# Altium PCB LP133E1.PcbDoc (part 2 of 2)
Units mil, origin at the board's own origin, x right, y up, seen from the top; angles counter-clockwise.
Board outline 3991.15 x 4704.13 mil, 4 copper layers (Top Layer, L02_GND1, L03_GND2, Bottom Layer), stack 58.396 mil thick; 74 components, 22 nets, 180 pads, 42 vias.
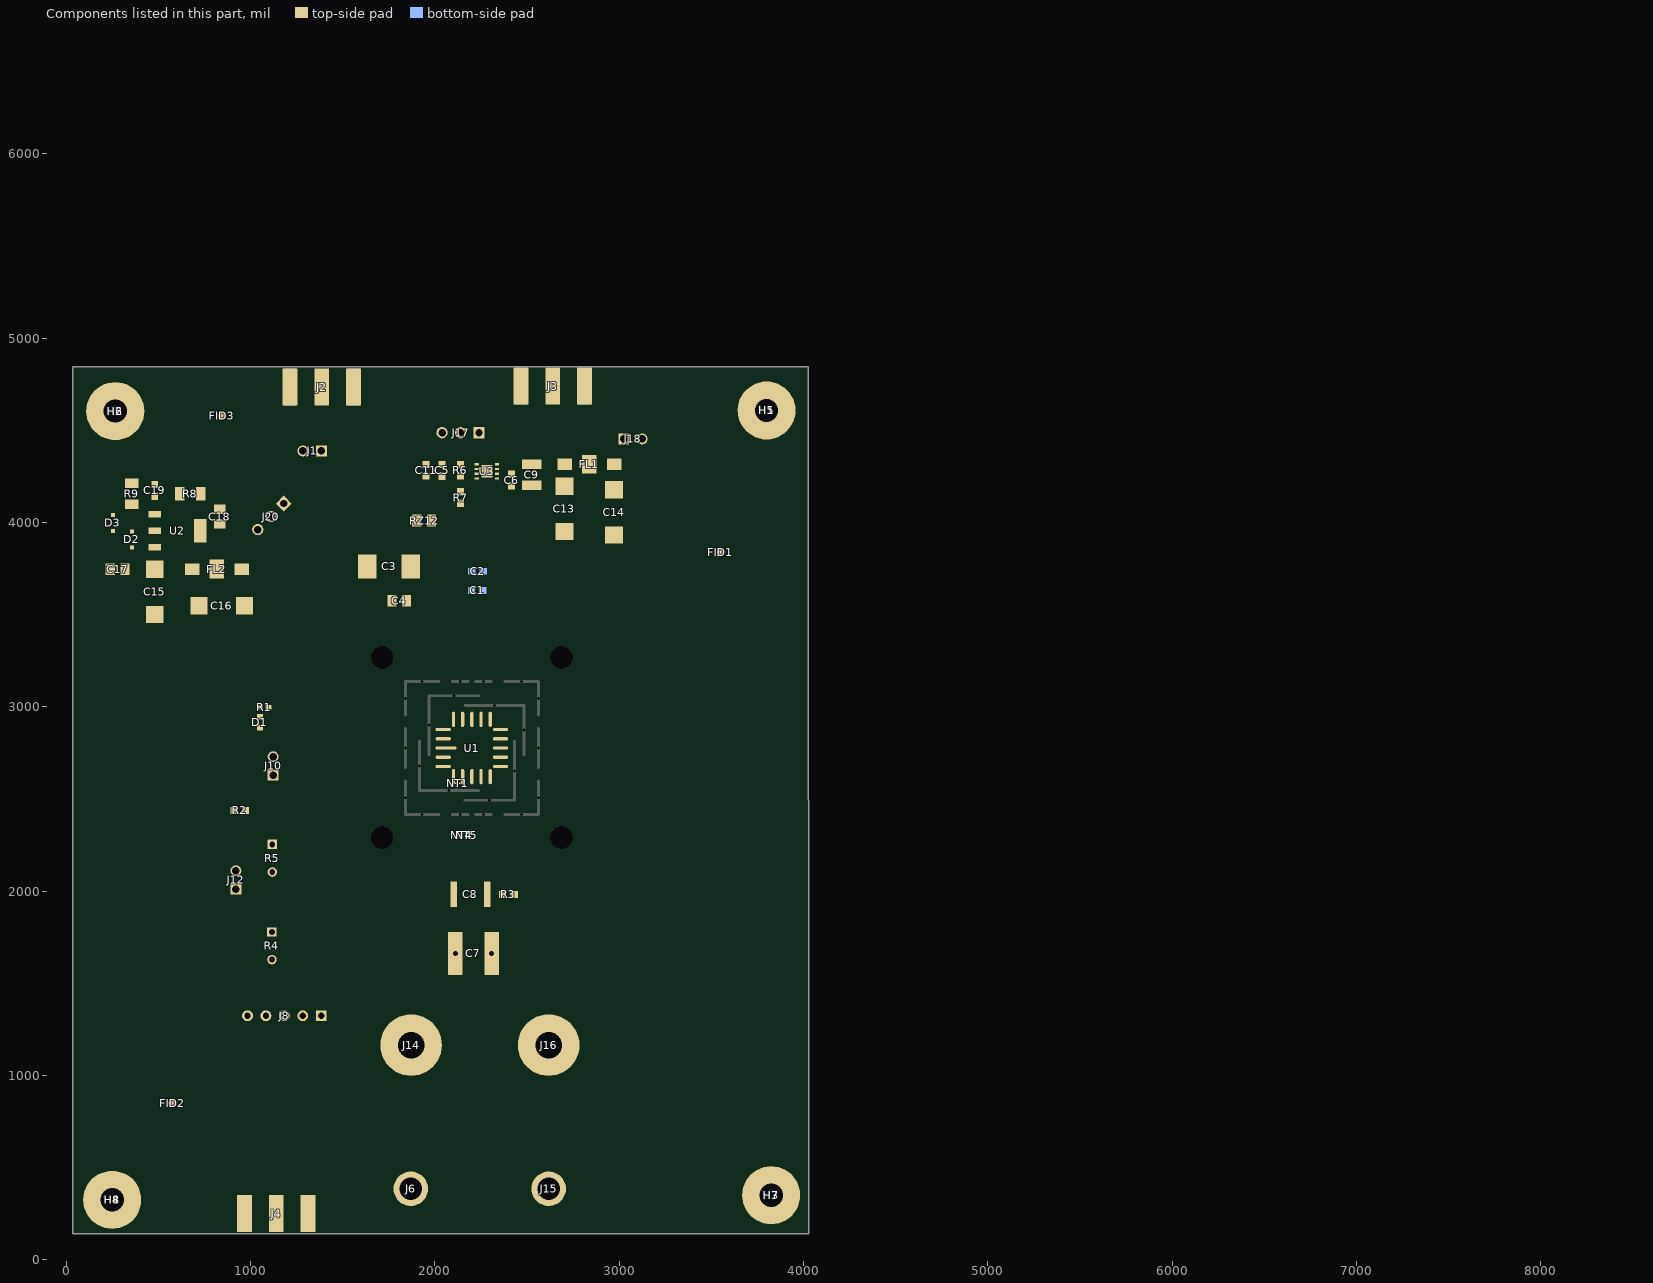
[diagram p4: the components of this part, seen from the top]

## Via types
v1: diameter 24, hole 12, Top Layer to Bottom Layer, tented both sides, 19 vias
v2: diameter 34, hole 16, Top Layer to Bottom Layer, tented both sides, 9 vias
v3: diameter 24, hole 8, Top Layer to Bottom Layer, tented both sides, 6 vias
v4: diameter 19.68, hole 7.87, Top Layer to Bottom Layer, 4 vias
v5: diameter 16, hole 8, Top Layer to Bottom Layer, tented both sides, 4 vias

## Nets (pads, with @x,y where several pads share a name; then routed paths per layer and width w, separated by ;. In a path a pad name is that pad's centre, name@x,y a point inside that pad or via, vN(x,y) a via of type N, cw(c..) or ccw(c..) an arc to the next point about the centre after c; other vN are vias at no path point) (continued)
copper on no net: | length 438086.5
  Top Layer w1: 5606.42,5272.44 5994.78,5660.8 ; 5606.42,5309.09 5958.14,5660.8 ; 5606.41,5345.73 5921.49,5660.81 ; 5606.41,5382.37 5884.85,5660.81 ; 5606.41,5419.01 5848.2,5660.81 ; 5606.4,5455.65 5811.55,5660.81 ; 5606.4,5492.3 5774.91,5660.81 ; 5606.39,5528.94 5738.26,5660.81 ; 5606.39,5565.58 5701.62,5660.81 ; 5606.39,5602.22 5664.97,5660.81 ; 5606.38,5638.86 5628.32,5660.81 ; 5606.47,4832.74 6434.54,5660.8 ; 5606.47,4869.38 6397.89,5660.8 ; 5606.46,4906.02 6361.24,5660.8 ; 5606.46,4942.66 6324.6,5660.8 ; 5606.45,4979.31 6287.95,5660.8 ; 5606.45,5015.95 6251.31,5660.8 ; 5606.45,5052.59 6214.66,5660.8 ; 5606.44,5089.23 6178.01,5660.8 ; 5606.44,5125.87 6141.37,5660.8 ; 5606.43,5162.52 6104.72,5660.8 ; 5606.43,5199.16 6068.08,5660.8 ; 5606.43,5235.8 6031.43,5660.8 ; 5606.52,4356.39 6910.93,5660.8 ; 5606.52,4393.03 6874.29,5660.8 ; 5606.51,4429.67 6837.64,5660.8 ; 5606.51,4466.31 6801,5660.8 ; 5606.51,4502.96 6764.35,5660.8 ; 5606.5,4539.6 6727.7,5660.8 ; 5606.5,4576.24 6691.06,5660.8 ; 5606.49,4612.88 6654.41,5660.8 ; 5606.49,4649.53 6617.77,5660.8 ; 5606.49,4686.17 6581.12,5660.8 ; 5606.48,4722.81 6544.47,5660.8 ; 5606.48,4759.45 6507.83,5660.8 ; 5606.47,4796.09 6471.18,5660.8 ; 5606.57,3916.68 7350.68,5660.8 ; 5606.57,3953.32 7314.04,5660.8 ; 5606.56,3989.97 7277.39,5660.8 ; 5606.56,4026.61 7240.75,5660.8 ; 5606.55,4063.25 7204.1,5660.8 ; 5606.55,4099.89 7167.45,5660.8 ; 5606.55,4136.54 7130.81,5660.8 ; 5606.54,4173.18 7094.16,5660.8 ; 5606.54,4209.82 7057.52,5660.8 ; 5606.53,4246.46 7020.87,5660.8 ; 5606.53,4283.1 6984.22,5660.8 ; 5606.53,4319.75 6947.58,5660.8 ; 5606.62,3440.33 7827.08,5660.79 ; 5606.62,3476.98 7790.44,5660.79 ; 5606.62,3513.62 7753.79,5660.79 ; 5606.61,3550.26 7717.14,5660.79 ; 5606.61,3586.9 7680.5,5660.79 ; 5606.6,3623.54 7643.85,5660.79 ; 5606.6,3660.19 7607.21,5660.79 ; 5606.6,3696.83 7570.56,5660.79 ; 5606.59,3733.47 7533.91,5660.79 ; 5606.59,3770.11 7497.27,5660.79 ; 5606.58,3806.76 7460.62,5660.79 ; 5606.58,3843.4 7423.98,5660.8 ; 5606.58,3880.04 7387.33,5660.8 ; 5606.67,3000.63 8266.83,5660.79 ; 5606.67,3037.27 8230.19,5660.79 ; 5606.66,3073.91 8193.54,5660.79 ; 5606.66,3110.55 8156.9,5660.79 ; 5606.66,3147.2 8120.25,5660.79 ; 5606.65,3183.84 8083.6,5660.79 ; 5606.65,3220.48 8046.96,5660.79 ; 5606.64,3257.12 8010.31,5660.79 ; 5606.64,3293.77 7973.67,5660.79 ; 5606.64,3330.41 7937.02,5660.79 ; 5606.63,3367.05 7900.37,5660.79 ; 5606.63,3403.69 7863.73,5660.79 ; 5606.72,2524.28 8424.78,5342.33 ; 5606.72,2560.92 8424.77,5378.97 ; 5606.72,2597.56 8424.77,5415.62 ; 5606.71,2634.21 8424.76,5452.26 ; 5606.71,2670.85 8424.76,5488.9 ; 5606.7,2707.49 8424.75,5525.54 ; 5606.7,2744.13 8424.74,5562.18 ; 5606.7,2780.77 8424.74,5598.82 ; 5606.69,2817.42 8424.73,5635.46 ; 5606.69,2854.06 8413.42,5660.79 ; 5606.68,2890.7 8376.77,5660.79 ; 5606.68,2927.34 8340.13,5660.79 ; 5606.68,2963.99 8303.48,5660.79 ; 5606.74,2341.07 8424.81,5159.13 ; 5606.74,2377.71 8424.8,5195.77 ; 5606.74,2414.35 8424.8,5232.41 ; 5606.73,2451 8424.79,5269.05 ; 5606.73,2487.64 8424.78,5305.69 ; 5639.6,2337.28 8424.81,5122.49 ; 5676.25,2337.28 8424.82,5085.85 ; 5712.9,2337.28 8424.83,5049.21 ; 5749.54,2337.28 8424.83,5012.57 ; 5786.19,2337.28 8424.84,4975.93 ; 5822.83,2337.28 8424.84,4939.29 ; 5859.48,2337.28 8424.85,4902.65 ; 5896.13,2337.28 8424.85,4866.01 ; 5932.77,2337.28 8424.86,4829.37 ; 5969.42,2337.28 8424.87,4792.73 ; 6006.07,2337.28 8424.87,4756.09 ; 6042.71,2337.28 8424.88,4719.45 ; 6079.36,2337.28 8424.88,4682.81 ; 6116,2337.28 8424.89,4646.17 ; 6152.65,2337.28 8424.9,4609.53 ; 6189.3,2337.28 8424.9,4572.89 ; 6225.94,2337.28 8424.91,4536.25 ; 6262.59,2337.28 8424.91,4499.61 ; 6299.24,2337.28 8424.92,4462.97 ; 6335.88,2337.28 8424.92,4426.32 ; 6372.53,2337.28 8424.93,4389.68 ; 6409.17,2337.28 8424.94,4353.04 ; 6445.82,2337.28 8424.94,4316.4 ; 6482.47,2337.28 8424.95,4279.76 ; 6519.11,2337.28 8424.95,4243.12 ; 6555.76,2337.28 8424.96,4206.48 ; 6592.4,2337.28 8424.97,4169.84 ; 6629.05,2337.28 8424.97,4133.2 ; 6665.7,2337.28 8424.98,4096.56 ; 6702.34,2337.28 8424.98,4059.92 ; 6738.99,2337.28 8424.99,4023.28 ; 6775.64,2337.28 8424.99,3986.64 ; 6812.28,2337.28 8425,3950 ; 6848.93,2337.28 8425.01,3913.36 ; 6885.57,2337.28 8425.01,3876.72 ; 6922.22,2337.28 8425.02,3840.08 ; 6958.87,2337.28 8425.02,3803.44 ; 6995.51,2337.28 8425.03,3766.8 ; 7032.16,2337.28 8425.03,3730.16 ; 7068.81,2337.28 8425.04,3693.52 ; 7105.45,2337.28 8425.05,3656.88 ; 7142.1,2337.28 8425.05,3620.24 ; 7178.74,2337.28 8425.06,3583.6 ; 7215.39,2337.28 8425.06,3546.96 ; 7252.04,2337.28 8425.07,3510.32 ; 7288.68,2337.28 8425.08,3473.68 ; 7325.33,2337.28 8425.08,3437.03 ; 7361.97,2337.28 8425.09,3400.39 ; 7398.62,2337.28 8425.09,3363.75 ; 7435.27,2337.28 8425.1,3327.11 ; 7471.91,2337.28 8425.1,3290.47 ; 7508.56,2337.28 8425.11,3253.83 ; 7545.21,2337.28 8425.12,3217.19 ; 7581.85,2337.28 8425.12,3180.55 ; 7618.5,2337.28 8425.13,3143.91 ; 7655.14,2337.28 8425.13,3107.27 ; 7691.79,2337.28 8425.14,3070.63 ; 7728.44,2337.28 8425.15,3033.99 ; 7733.6,5683.21 7802.27,5751.88 7875.56,5825.17 7948.85,5898.47 8022.15,5971.76 8095.44,6045.05 8168.73,6118.34 8242.02,6191.64 8315.32,6264.93 8388.61,6338.22 8425.26,6374.87 ; 7733.6,5719.86 7765.62,5751.88 7838.92,5825.17 7912.21,5898.47 7985.5,5971.76 8058.79,6045.05 8132.09,6118.34 8205.38,6191.64 8278.67,6264.93 8351.96,6338.22 8425.26,6411.51 ; 7733.6,5756.5 7802.27,5825.17 7875.56,5898.47 7948.85,5971.76 8022.15,6045.05 8095.44,6118.34 8168.73,6191.64 8242.02,6264.93 8315.32,6338.22 8388.61,6411.51 8425.26,6448.16 ; 7733.6,5793.15 7765.62,5825.17 7838.92,5898.47 7912.21,5971.76 7985.5,6045.05 8058.79,6118.34 8132.09,6191.64 8205.38,6264.93 8278.67,6338.22 8351.96,6411.51 8425.26,6484.81 ; 7733.6,5829.8 7802.27,5898.47 7875.56,5971.76 7948.85,6045.05 8022.15,6118.34 8095.44,6191.64 8168.73,6264.93 8242.02,6338.22 8315.32,6411.51 8388.61,6484.81 ; 7733.6,5866.44 7765.62,5898.47 7838.92,5971.76 7912.21,6045.05 7985.5,6118.34 8058.79,6191.64 8132.09,6264.93 8205.38,6338.22 8278.67,6411.51 8351.96,6484.81 ; 7733.6,5903.09 7802.27,5971.76 7875.56,6045.05 7948.85,6118.34 8022.15,6191.64 8095.44,6264.93 8168.73,6338.22 8242.02,6411.51 8315.32,6484.81 ; 7733.6,5939.74 7765.62,5971.76 7838.92,6045.05 7912.21,6118.34 7985.5,6191.64 8058.79,6264.93 8132.09,6338.22 8205.38,6411.51 8278.67,6484.81 ; 7733.6,5976.38 7802.27,6045.05 7875.56,6118.34 7948.85,6191.64 8022.15,6264.93 8095.44,6338.22 8168.73,6411.51 8242.02,6484.81 ; 7733.6,6013.03 7765.62,6045.05 7838.92,6118.34 7912.21,6191.64 7985.5,6264.93 8058.79,6338.22 8132.09,6411.51 8205.38,6484.81 ; 7733.6,6049.67 7802.27,6118.34 7875.56,6191.64 7948.85,6264.93 8022.15,6338.22 8095.44,6411.51 8168.73,6484.81 ; 7733.6,6086.32 7765.62,6118.34 7838.92,6191.64 7912.21,6264.93 7985.5,6338.22 8058.79,6411.51 8132.09,6484.81 ; 7733.6,6122.97 7802.27,6191.64 7875.56,6264.93 7948.85,6338.22 8022.15,6411.51 8095.44,6484.81 ; 7733.6,6159.61 7765.62,6191.64 7838.92,6264.93 7912.21,6338.22 7985.5,6411.51 8058.79,6484.81 ; 7733.6,6196.26 7802.27,6264.93 7875.56,6338.22 7948.85,6411.51 8022.15,6484.81 ; 7733.6,6232.91 7765.62,6264.93 7838.92,6338.22 7912.21,6411.51 7985.5,6484.81 ; 7733.6,6269.55 7802.27,6338.22 7875.56,6411.51 7948.85,6484.81 ; 7733.6,6306.2 7765.62,6338.22 7838.92,6411.51 7912.21,6484.81 ; 7733.6,6342.84 7802.27,6411.51 7875.56,6484.81 ; 7733.6,6379.49 7765.62,6411.51 7838.92,6484.81 ; 7733.6,6416.14 7802.27,6484.81 ; 7733.6,6452.78 7765.62,6484.81 ; 7765.08,2337.28 8425.15,2997.35 ; 7765.62,5678.59 7838.92,5751.88 7912.21,5825.17 7985.5,5898.47 8058.79,5971.76 8132.09,6045.05 8205.38,6118.34 8278.67,6191.64 8351.96,6264.93 8425.26,6338.22 ; 7801.73,2337.28 8425.16,2960.71 ; 7802.27,5678.59 7875.56,5751.88 7948.85,5825.17 8022.15,5898.47 8095.44,5971.76 8168.73,6045.05 8242.02,6118.34 8315.32,6191.64 8388.61,6264.93 8425.26,6301.57 ; 7838.38,2337.28 8425.16,2924.07 ; 7838.92,5678.59 7912.21,5751.88 7985.5,5825.17 8058.79,5898.47 8132.09,5971.76 8205.38,6045.05 8278.67,6118.34 8351.96,6191.64 8425.26,6264.93 ; 7875.02,2337.28 8425.17,2887.43 ; 7875.56,5678.59 7948.85,5751.88 8022.15,5825.17 8095.44,5898.47 8168.73,5971.76 8242.02,6045.05 8315.32,6118.34 8388.61,6191.64 8425.26,6228.28 ; 7911.67,2337.28 8425.17,2850.79 ; 7912.21,5678.59 7985.5,5751.88 8058.79,5825.17 8132.09,5898.47 8205.38,5971.76 8278.67,6045.05 8351.96,6118.34 8425.26,6191.64 ; 7948.31,2337.28 8425.18,2814.15 ; 7948.85,5678.59 8022.15,5751.88 8095.44,5825.17 8168.73,5898.47 8242.02,5971.76 8315.32,6045.05 8388.61,6118.34 8425.26,6154.99 ; 7984.96,2337.28 8425.19,2777.51 ; 7985.5,5678.59 8058.79,5751.88 8132.09,5825.17 8205.38,5898.47 8278.67,5971.76 8351.96,6045.05 8425.26,6118.34 ; 8021.61,2337.28 8425.19,2740.87 ; 8022.15,5678.59 8095.44,5751.88 8168.73,5825.17 8242.02,5898.47 8315.32,5971.76 8388.61,6045.05 8425.26,6081.7 ; 8058.25,2337.28 8425.2,2704.23 ; 8058.79,5678.59 8132.09,5751.88 8205.38,5825.17 8278.67,5898.47 8351.96,5971.76 8425.26,6045.05 ; 8094.9,2337.28 8425.2,2667.59 ; 8095.44,5678.59 8168.73,5751.88 8242.02,5825.17 8315.32,5898.47 8388.61,5971.76 8425.26,6008.4 ; 8131.55,2337.28 8425.21,2630.95 ; 8132.09,5678.59 8205.38,5751.88 8278.67,5825.17 8351.96,5898.47 8425.26,5971.76 ; 8168.19,2337.28 8425.22,2594.31 ; 8168.73,5678.59 8242.02,5751.88 8315.32,5825.17 8388.61,5898.47 8425.26,5935.11 ; 8204.84,2337.28 8425.22,2557.67 ; 8205.38,5678.59 8278.67,5751.88 8351.96,5825.17 8425.26,5898.47 ; 8241.48,2337.28 8425.23,2521.02 ; 8242.02,5678.59 8315.32,5751.88 8388.61,5825.17 8425.26,5861.82 ; 8278.13,2337.28 8425.23,2484.38 ; 8278.67,5678.59 8351.96,5751.88 8425.26,5825.17 ; 8314.78,2337.28 8425.24,2447.74 ; 8315.32,5678.59 8388.61,5751.88 8425.26,5788.53 ; 8351.42,2337.28 8425.24,2411.1 ; 8351.96,5678.59 8425.26,5751.88 ; 8388.07,2337.28 8425.25,2374.46 ; 8388.61,5678.59 8425.26,5715.23
  Top Layer w15: 5606.38,5751.88 5864.53,5751.88 6440.17,5751.88 6973.08,5751.88 7377.76,5751.88 7733.6,5751.88 8425.26,5751.88 ; 5606.38,5825.17 5864.53,5825.17 6440.17,5825.17 6973.08,5825.17 7377.76,5825.17 7733.6,5825.17 8425.26,5825.17 ; 5606.38,5898.47 5864.53,5898.47 6440.17,5898.47 6973.08,5898.47 7377.76,5898.47 7733.6,5898.47 8425.26,5898.47 ; 5606.38,5971.76 5864.53,5971.76 6440.17,5971.76 6973.08,5971.76 7377.76,5971.76 7733.6,5971.76 8425.26,5971.76 ; 5606.38,6045.05 5864.53,6045.05 6440.17,6045.05 6973.08,6045.05 7377.76,6045.05 7733.6,6045.05 8425.26,6045.05 ; 5606.38,6118.34 5864.53,6118.34 6440.17,6118.34 6973.08,6118.34 7377.76,6118.34 7733.6,6118.34 8425.26,6118.34 ; 5606.38,6191.64 5864.53,6191.64 6440.17,6191.64 6973.08,6191.64 7377.76,6191.64 7733.6,6191.64 8425.26,6191.64 ; 5606.38,6264.93 5864.53,6264.93 6440.17,6264.93 6973.08,6264.93 7377.76,6264.93 7733.6,6264.93 8425.26,6264.93 ; 5606.38,6338.22 5864.53,6338.22 6440.17,6338.22 6973.08,6338.22 7377.76,6338.22 7733.6,6338.22 8425.26,6338.22 ; 5606.38,6411.51 5864.53,6411.51 6440.17,6411.51 6973.08,6411.51 7377.76,6411.51 7733.6,6411.51 8425.26,6411.51 ; 5606.38,6484.81 8425.26,6484.81 ; 5864.53,6558.1 5864.53,5678.59 ; 6440.17,6558.1 6440.17,5678.59 ; 6973.08,6558.1 6973.08,5678.59 ; 7377.76,6558.1 7377.76,5678.59 ; 7733.6,6558.1 7733.6,5678.59 ; 5864.53,5678.59 5606.38,5678.59 5606.38,6558.1 8425.26,6558.1 8425.26,5678.59 7733.6,5678.59 ; 5864.53,5678.59 6440.17,5678.59 ; 6440.17,5678.59 6973.08,5678.59 ; 6973.08,5678.59 7377.76,5678.59 ; 7377.76,5678.59 7733.6,5678.59 ; 5606.38,5660.27 5606.74,2337.82 8425.26,2337.82 8424.73,5660.22 5606.38,5660.27

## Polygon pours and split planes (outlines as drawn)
GND on L03_GND2 "L03_GND2_GND_P020" (solid, remove dead copper, pour order 20): 2477.05,3275.49 2395.46,3193.9 1799.04,3193.9 1764.49,3159.35 1764.49,2892.42 1716.69,2844.62 1493.09,2844.62 1476.15,2827.68 1476.15,2076.12 1501.15,2051.12 3284.73,2051.12 3389.56,2155.95 3389.56,3376.67 3265.12,3501.12 2515.15,3501.12 2477.05,3463.02
GND on L03_GND2 "NONET_L-01_P-001" (solid, remove dead copper, pour order 22): 1710.95,2873.12 1733.65,2895.82 1733.65,3175.45 1789.32,3231.12 2379.14,3231.12 2429.61,3281.59 2429.61,3484.86 2355.32,3559.15 1148.55,3559.15 1045.55,3456.14 1045.55,2919.97 1092.4,2873.12
GND_HET on Top Layer "TOP_LAYER_GND_HET_P037" (solid, remove dead copper, pour order 37): 1272.92,4834.09 1272.92,4830.5 1329.57,4773.48 1325.51,4327.26 890.81,3892.56 890.81,3462.66 818.15,3390 111.55,3390 111.55,4069.39 876.25,4834.09
GND on Top Layer "TOP_LAYER_GND_P035" (solid, remove dead copper, pour order 35): 2501.65,2475.62 2501.65,3000.16 2501.65,3076.62 1900.65,3076.62 1900.65,2949.12 1860.65,2949.12 1854.89,2954.88 1854.89,3110.85 1873.07,3129.03 1903.07,3129.03 1929.36,3155.32 2356,3155.32 2477.05,3276.37 2477.05,3463.02 2515.15,3501.12 3265.22,3501.12 3389.38,3376.95 3389.38,1813.69 2861.04,1285.34 970.2,1285.34 872.62,1382.92 872.62,2653.4 1063.84,2844.62 1898.65,2844.62 1900.65,2842.62 1900.65,2475.62
HET+ on Top Layer "TOP_LAYER_HET+_P043" (solid, remove dead copper, pour order 43): 1508.08,3792.95 1540.13,3825 1755.21,3825 1807.53,3772.69 1807.53,3518.36 1774.03,3484.86 1547.79,3484.86 1508.08,3524.56
GND on Top Layer "NONET_L-01_P-001" (solid, remove dead copper, pour order 41): 1943.18,3583.08 2111.13,3415.13 2111.13,3241.3 2158.53,3194.2 2369.39,3194.2 2429.61,3254.41 2429.61,3584.62 2501.71,3654.02 3662.03,3654.02 3975.75,3967.74 3975.75,4773.82 3915.48,4834.09 2255.34,4834.09 1943.18,4452.31
PWR_EXT on Top Layer "TOP_LAYER_PWR_EXT_P005" (solid, remove dead copper, pour order 5): 2501.71,4557.26 2597.21,4652.75 2679.21,4652.75 2772.57,4559.38 2772.57,4557.26 2995.42,4557.26 3064.57,4488.11 3064.17,4133.16 3036.75,4105.74 2927.34,4105.74 2927.34,4107.7 2906.6,4128.44 2906.87,4360.45 2851.31,4416 2249.19,4416 2208.85,4456.35 2208.85,4519.08 2247.02,4557.26
LDO on Top Layer "TOP_LAYER_LDO_P006" (solid, remove dead copper, pour order 6): 1913.21,4283.27 1913.4,4283.46 2237.18,4283.46 2237.18,4345.22 2060.26,4522.14 2019.4,4522.14 2019.4,4520.86 1913.05,4414.5 1913.05,4285.08
GND_HET on Top Layer "NONET_L-01_P-001" (solid, remove dead copper, pour order 29): 1598.71,4698.06 1927.66,4369.11 1931.4,4362.77 1931.4,3404.81 2047.11,3289.1 2047.11,3207.49 2041.62,3202 2041.62,3181.47 2035.77,3175.62 1918.18,3175.62 1918.18,3253.54 1918.3,3253.66 1519.26,3652.71 1519.26,4698.06
HEAT_LDO on Top Layer "TOP_LAYER_HEAT_LDO_P036" (solid, remove dead copper, pour order 36): 1120.61,3913.05 1120.61,3960.9 1064.46,4017.05 234.76,4017.05 205.85,3988.14 205.85,3930.37 242.49,3893.73 951.84,3893.73 1084.4,3893.73
GND_HET on Bottom Layer "BOTTOM_LAYER_GND_HET_P044" (solid, remove dead copper, pour order 44): 1097.05,4736.04 1179.62,4818.6 1582.77,4818.6 1633.37,4768.01 1633.37,4330.63 1583.89,4281.15 1127.09,4281.15 1097.05,4311.2
GND on Bottom Layer "BOTTOM_LAYER_GND_P031" (solid, remove dead copper, pour order 31): 2477.05,3275.49 2395.46,3193.9 1799.04,3193.9 1764.49,3159.35 1764.49,2892.42 1716.69,2844.62 1493.09,2844.62 1476.15,2827.68 1476.15,2076.12 1501.15,2051.12 3401.41,2051.12 3569.95,2219.66 3569.95,3511.04 3303.25,3777.75 2623.74,3777.75 2477.05,3631.07
GND on Bottom Layer "NONET_L-01_P-001" (solid, remove dead copper, pour order 32): 1710.95,2873.12 1733.65,2895.82 1733.65,3175.45 1789.32,3231.12 2379.14,3231.12 2429.61,3281.59 2429.61,3761.5 2397.11,3794.01 1320.98,3794.01 1045.55,3518.58 1045.55,2919.97 1092.4,2873.12
HET+ on L02_GND1 "L02_GND1_HET+_P042" (solid, remove dead copper, pour order 42): 2030.15,3241.3 1712.31,3559.15 1486.46,3559.15 1062.83,3982.77 1062.83,4053.37 1090.39,4080.93 1151.73,4080.93 1407.66,3825 1792.4,3825 2134.31,3483.09 2134.31,3264.48 2111.13,3241.3 2059.19,3241.3
GND on L02_GND1 "L02_GND1_GND_P033" (solid, remove dead copper, pour order 33): 2477.05,3275.49 2395.46,3193.9 1799.04,3193.9 1764.49,3159.35 1764.49,2892.42 1716.69,2844.62 1493.09,2844.62 1476.15,2827.68 1476.15,2076.12 2283.28,1268.99 3450.93,1268.99 3600,1418.06 3600,3168.08 3266.96,3501.12 2515.15,3501.12 2477.05,3463.02

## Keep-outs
Keep-Out Layer:
  text ".Layer_Name" at -973,-1908.49 h60

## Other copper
Top Layer:
  pour cut-out: 784.21,4575.55 ccw(c844.21,4575.55) 844.21,4515.55 ccw(c844.21,4575.55) 904.21,4575.55 ccw(c844.21,4575.55) 844.21,4635.55 ccw(c844.21,4575.55)
  pour cut-out: 513.34,848.74 ccw(c573.34,848.74) 573.34,788.74 ccw(c573.34,848.74) 633.34,848.74 ccw(c573.34,848.74) 573.34,908.74 ccw(c573.34,848.74)
  pour cut-out: 3489.04,3839.99 ccw(c3549.04,3839.99) 3549.04,3779.99 ccw(c3549.04,3839.99) 3609.04,3839.99 ccw(c3549.04,3839.99) 3549.04,3899.99 ccw(c3549.04,3839.99)
  region net HEAT_EXT: 1181.26,3943.29 1181.26,4147.69 1346.76,4313.18 1346.76,4709.51 1426.79,4709.51 1493.09,4643.2 1494.76,4643.2 1494.76,3921.37 1243.4,3670.01 1073.34,3518.58 928.7,3518.58 900.84,3546.44 900.84,3766.26 912.38,3777.8 1045.78,3777.8
  pour cut-out: 2222.17,2433.97 2222.17,2432.59 2180.17,2432.59 2180.17,2433.97
  pour cut-out: 2022.15,3118.27 2022.15,3119.64 2096.17,3119.64 2096.17,3118.26
  pour cut-out: 2180.17,3118.26 2180.17,3119.64 2222.17,3119.64 2222.17,3118.26
  pour cut-out: 2352.01,3117.49 2352.01,3118.87 2381.51,3118.87 2381.51,3117.49
  region net REFZ_F: 2093.63,2295.31 2110.01,2311.69 2110.01,2355.65 2081.75,2383.91 2045.05,2383.91 2038.82,2377.68 2038.82,2336.4 2038.82,2279.25 2038.82,2253.82 2046.38,2246.27 2084.71,2246.27 2093.03,2254.59 2093.63,2291.73
  pour cut-out: 1024.44,2908.1 1024.44,2928.16 1075.94,2928.16 1075.94,2908.1
  text "Layer" at 5653.03,6503.13 h36.65
  text "Name" at 5911.17,6503.13 h36.65
  text "Material" at 6486.82,6503.13 h36.65
  text "Thickness" at 7019.72,6503.13 h36.65
  text "Constant" at 7424.41,6503.13 h36.65
  text "Board Layer Stack" at 7780.25,6503.13 h36.65
  text "Top Overlay" at 5911.17,6429.84 h36.65
  text "Top Solder" at 5911.17,6356.54 h36.65
  text "Solder Resist" at 6486.82,6356.54 h36.65
  text "1.00mil" at 7019.72,6356.54 h36.65
  text "3.5" at 7424.41,6356.54 h36.65
  text "1" at 5653.03,6283.25 h36.65
  text "Top Layer" at 5911.17,6283.25 h36.65
  text "COPPER" at 6486.82,6283.25 h36.65
  text "1.40mil" at 7019.72,6283.25 h36.65
  text "Dielectric 1" at 5911.17,6209.96 h36.65
  text "FR4 HIGH TG" at 6486.82,6209.96 h36.65
  text "4.17mil" at 7019.72,6209.96 h36.65
  text "4.1" at 7424.41,6209.96 h36.65
  text "2" at 5653.03,6136.67 h36.65
  text "L02_GND1" at 5911.17,6136.67 h36.65
  text "COPPER" at 6486.82,6136.67 h36.65
  text "1.40mil" at 7019.72,6136.67 h36.65
  text "Dielectric 2" at 5911.17,6063.37 h36.65
  text "FR4 HIGH TG" at 6486.82,6063.37 h36.65
  text "44.45mil" at 7019.72,6063.37 h36.65
  text "4.8" at 7424.41,6063.37 h36.65
  text "3" at 5653.03,5990.08 h36.65
  text "L03_GND2" at 5911.17,5990.08 h36.65
  text "COPPER" at 6486.82,5990.08 h36.65
  text "1.40mil" at 7019.72,5990.08 h36.65
  text "Dielectric 3" at 5911.17,5916.79 h36.65
  text "FR4 HIGH TG" at 6486.82,5916.79 h36.65
  text "4.17mil" at 7019.72,5916.79 h36.65
  text "4.1" at 7424.41,5916.79 h36.65
  text "4" at 5653.03,5843.5 h36.65
  text "Bottom Layer" at 5911.17,5843.5 h36.65
  text "COPPER" at 6486.82,5843.5 h36.65
  text "1.40mil" at 7019.72,5843.5 h36.65
  text "Bottom Solder" at 5911.17,5770.2 h36.65
  text "Solder Resist" at 6486.82,5770.2 h36.65
  text "1.00mil" at 7019.72,5770.2 h36.65
  text "3.5" at 7424.41,5770.2 h36.65
  text "Bottom Overlay" at 5911.17,5696.91 h36.65
  text ".Layer_Name" at -973,-1908.49 h60
L02_GND1:
  pour cut-out: 2058.87,2394.96 2080,2373.82 2079.97,2373.85 ccw(c2088.85,2382.67) 2088.85,2370.16 2133.19,2370.16 2160.32,2343.03 2160.32,2329.23 ccw(c2172.83,2329.23) 2185.35,2329.23 2185.35,2348.21 ccw(c2172.83,2348.21) 2181.65,2357.09 2181.68,2357.06 2147.22,2391.52 2147.25,2391.5 ccw(c2138.37,2382.67) 2138.37,2395.19 2094.03,2395.19 2080.23,2408.99 2080.23,2461.33 2120,2501.1 2249.49,2501.1 ccw(c2249.49,2513.62) 2258.37,2504.8 2258.34,2504.77 2280.14,2526.56 2280.11,2526.53 ccw(c2271.29,2535.41) 2283.8,2535.41 2283.8,2849.44 2339.51,2905.14 ccw(c2330.66,2913.99) 2343.17,2913.99 ccw(c2330.66,2913.99) 2321.81,2922.84 2262.44,2863.47 2262.46,2863.5 ccw(c2271.29,2854.62) 2258.77,2854.62 2258.77,2540.59 2244.31,2526.13 2114.82,2526.13 ccw(c2114.82,2513.62) 2105.94,2522.44 2105.97,2522.47 2058.87,2475.36 2058.89,2475.39 ccw(c2067.72,2466.51) 2055.2,2466.51 2055.2,2403.81 ccw(c2067.72,2403.81)
  text ".Layer_Name" at -958.47,-1915.72 h60
L03_GND2:
  text ".Layer_Name" at -972.97,-1937.52 h60
Bottom Layer:
  region net GND: 1480.57,3031.9 1480.57,2930.71 1476.64,2926.78 1460.26,2943.17 1460.26,3011.59
  region net GND: 2414.61,3500.63 2398.23,3517.01 2332.97,3517.01 2251.33,3517.01 2250.98,3517.01 2234.59,3500.63 2238.52,3496.7 2414.61,3496.7
  region net GND: 1974.61,3517.38 1957.17,3499.93 1959.43,3497.66 2135.15,3497.66 2135.15,3517.38
  text ".Layer_Name" at -973,-1908.49 h60
Multi-Layer:
  pour cut-out: 2156.55,2329.23 ccw(c2172.83,2329.23) 2172.83,2312.95 ccw(c2172.83,2329.23) 2189.11,2329.23 ccw(c2172.83,2329.23) 2172.83,2345.51 ccw(c2172.83,2329.23)
  pour cut-out: 1900.65,2475.62 1900.65,3076.62 2501.65,3076.62 2501.65,2475.62

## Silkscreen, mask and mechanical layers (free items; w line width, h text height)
Top Overlay:
  drawing of 12 lines, arcs and shapes, not listed
  text "VIN" at 2933.34,4523.27 h30
  text "GND" at 3131,4521.65 h30
  text "Bypass" at 2325.06,4481.18 h30
  text "LDO" at 1895.06,4472.32 h30
  text "GND" at 1202.76,4457.74 h30
  text "Heater VIN" at 1392.77,4455.1 h30
  text "Bypass" at 1239.34,4146.4 h30
  text "LDO" at 912.61,3888.37 h30
  text "Output Stable" at 680.85,2720.46 h30
  text "REF80" at 2721.62,2659.94 h50 r90
  text "GND" at 956.65,2608.06 h30
  text "Divider Out" at 533.3,2004.34 h30
  text "GND" at 756.64,1898.79 h30
  text "GND" at 1001.85,1150.6 h30 r90
  text "REFZ_F" at 1202.63,1080.17 h30 r90
  text "REFZ_S_P" at 1301.5,1027 h30 r90
  text "REFZ_S_N" at 1102.63,1021 h30 r90
  text "REFZ_S_N" at 1400,1021 h30 r90
  text "VREF Out" at 625.95,256 h30
  text "VREF-" at 2545.01,183 h30
  text "VREF+" at 1813.97,177 h30
  text ".Layer_Name" at -973,-1908.49 h60
Bottom Overlay:
  text ".Layer_Name" at -973,-1908.49 h60
Top Paste:
  drawing of 8 lines, arcs and shapes, not listed
  text ".Layer_Name" at -973,-1908.49 h60
Bottom Paste:
  text ".Layer_Name" at -973,-1908.49 h60
Top Solder:
  text ".Layer_Name" at -973,-1908.49 h60
  text ".Layer_Name" at -973,-1908.49 h60
Bottom Solder:
  text ".Layer_Name" at -973,-1908.49 h60
Drill Guide:
  text ".Layer_Name" at -973,-1908.49 h60
M1 Board Outline:
  lines w10: 36.73,4844.13 37.25,140 4027.88,140 4027.14,4844.07 36.73,4844.13 ; 1451.15,2026.12 1451.15,2026.12
  text ".Layer_Name" at -973,-1908.49 h60
M2 Board Dimensions:
  rectangle: -1633.07,-910.83 -1258.07,-785.83
  rectangle: -1758.07,-785.83 -1633.07,-660.83
  lines w7: -1758.07,-785.83 -758.07,-785.83 ; -1633.07,-910.83 -1633.07,-660.83 ; -1508.07,-910.83 -1508.07,-660.83 ; -1258.07,-910.83 -1258.07,-660.83 ; -1008.07,-910.83 -1008.07,-660.83 ; -1758.07,-910.83 -1758.07,-660.83 -758.07,-660.83 -758.07,-910.83 -1758.07,-910.83
  text ".Layer_Name" at -973,-1908.49 h60
M3 3D STEP Top:
  text ".Layer_Name" at -973,-1908.49 h60
M4 3D STEP Bottom:
  text ".Layer_Name" at -973,-1908.49 h60
M5 Assembly Top:
  lines w5: 1621.19,2889.54 1651.19,2889.54 ; 1635.75,2874.54 1635.75,2889.54 ; 1635.78,2919.51 1635.78,2904.51 ; 1635.78,2904.51 1650.78,2904.51 1635.78,2889.51 1620.78,2904.51 1635.78,2904.51
  lines w10: -1842,-1980.17 4758,-1980.17 ; -1842,-1776.83 4760,-1776.83 ; -1842,-1573.5 -1842,-2183.5 2163,-2183.5 4760,-2183.5 4760,-1573.5 -1841.5,-1573.5 -1841.5,-2183.5 -266,-2183.5 ; 623,-2183.5 623,-1573.5 ; 1890,-1776.83 1890,-1573.5 ; 2730,-1776.83 2730,-1573.5 ; 3352,-2190 3352,-1987.17
  text "COMPONENTS MARKED 'DNP' SHOULD NOT BE POPULATED." at 4181.65,-1308.07 h60
  text "ASSEMBLY VARIANT:" at 4181.15,-1423.57 h60
  text ".VariantName" at 5217.15,-1423.57 h60
  text "PCB VIEWED FROM TOP SIDE" at -1778.5,-1705.67 h60
  text "BOARD #:" at 698,-1705.67 h60
  text ".PRJ_Number" at 1243.5,-1705.67 h60
  text "REV:" at 2088,-1705.67 h60
  text ".PCB_Rev" at 2379.5,-1705.67 h60
  text "SVN REV:" at 2926,-1705.67 h60
  text ".VersionControl_RevNumber" at 3432,-1705.67 h60
  text "TID #:" at 698,-1909 h60
  text ".TID" at 1243.5,-1909 h60
  text "PLOT NAME =" at -1778.5,-2114.34 h60
  text ".plot_File_Name" at -973,-2114.34 h60
  text "GENERATED    :" at 700,-2114.34 h60
  text ".Print_Date" at 1569.5,-2114.34 h60
  text ".Print_Time" at 2298.5,-2114.34 h60
  text "TEXAS INSTRUMENTS" at 3563,-2114.34 h60
M6 Assembly Bottom:
  lines w10: -1842.5,-1777.33 4759.5,-1777.33 ; -1840.5,-1980.67 4759.5,-1980.67 ; -434.5,-2190.5 -434.5,-1987.67 ; 187.5,-1777.33 187.5,-1574 ; 1027.5,-1777.33 1027.5,-1574 ; 2294.5,-2184 2294.5,-1574 ; 3183.5,-2184 4759,-2184 4759,-1574 -1842.5,-1574 -1842.5,-2184 754.5,-2184 4759.5,-2184 4759.5,-1574
  text "COMPONENTS MARKED 'DNP' SHOULD NOT BE POPULATED." at 9130.15,-1307.57 h60
  text ".VariantName" at 8086.15,-1423.57 h60
  text "ASSEMBLY VARIANT:" at 9125.15,-1423.57 h60
  text ".VersionControl_RevNumber" at -514.5,-1706.17 h60
  text "SVN REV:" at -8.5,-1706.17 h60
  text ".PCB_Rev" at 538,-1706.17 h60
  text "REV:" at 829.5,-1706.17 h60
  text ".PRJ_Number" at 1674,-1706.17 h60
  text "BOARD #:" at 2219.5,-1706.17 h60
  text "PCB VIEWED FROM BOTTOM SIDE" at 4696,-1706.17 h60
  text ".TID" at 1674,-1909.5 h60
  text "TID #:" at 2219.5,-1909.5 h60
  text "TEXAS INSTRUMENTS" at -645.5,-2114.84 h60
  text ".Print_Time" at 619,-2114.84 h60
  text ".Print_Date" at 1348,-2114.84 h60
  text "GENERATED    :" at 2217.5,-2114.84 h60
  text ".plot_File_Name" at 3890.5,-2114.84 h60
  text "PLOT NAME =" at 4696,-2114.84 h60
M9 Title Sheet:
  drawing of 57 lines, arcs and shapes, not listed
  text "1" at -810.16,6986.5 h70
  text "2" at 1685.5,6986.5 h70
  text "3" at 4174.84,6986.5 h70
  text "4" at 6681.51,6986.5 h70
  text "5" at 9180.5,6986.5 h70
  text "6" at 11685.5,6986.5 h70
  text "A" at -1966.5,5843.5 h70
  text "A" at 12833.5,5843.5 h70
  text "B" at -1966.5,3463.5 h70
  text "B" at 12833.5,3463.5 h70
  text "C" at -1966.5,1088.5 h70
  text "C" at 12833.5,1088.5 h70
  text "PROJECT TITLE:" at 9793.5,-772.5 h45
  text "REF80x_Breakout_CouponCard_Cut" at 9843.5,-905.83 h70
  text "DESIGNED FOR:" at 9793.5,-1073.5 h45
  text ".PRJ_Customer" at 9843.5,-1213.5 h70
  text "D" at -1966.5,-1281.5 h70
  text "D" at 12833.5,-1281.5 h70
  text "FILE NAME:" at 9793.5,-1373.5 h45
  text ".PCB_File_Name_No_Path" at 9843.5,-1493.5 h60
  text "Texas Instruments (TI) and/or its licensors do not warrant the accuracy or completeness of this specification" at 4824,-1655.34 h45
  text "ENGINEER:" at 9793.5,-1663.5 h45
  text "LAYOUT BY:" at 11298.5,-1663.5 h45
  text "or any information contained therein. TI and/or its licensors do not warrant that this design will meet" at 4779.01,-1768 h45
  text "Mahadev" at 9843.5,-1818.49 h70
  text "PACTRON" at 11349,-1818.49 h70
  text "the specifications, will be suitable for your application or fit for any particular purpose, or will operate in" at 4779.01,-1880.67 h45
  text ".Layer_Name" at -973,-1908.49 h60
  text "ALTIUM DESIGNER VERSION:" at 11298.5,-1973.5 h45
  text "an implementation. TI and/or its licensors do not warrant that the design is production worthy. You should" at 4779.01,-1993.33 h45
  text "completely validate and test your design implementation to confirm the system functionality for your application." at 4824,-2106 h45
  text ".print_Scale" at 9843.5,-2106.83 h70
  text ".Application_BuildNumber" at 11349,-2106.83 h70
  text "1" at -810.16,-2313.5 h70
  text "2" at 1685.5,-2313.5 h70
  text "3" at 4174.84,-2313.5 h70
  text "4" at 6681.51,-2313.5 h70
  text "5" at 9180.5,-2313.5 h70
  text "6" at 11685.5,-2313.5 h70
M10 Fab Notes:
  drawing of 189 lines, arcs and shapes, not listed
  text "DESIGN INFORMATION" at 10832.02,5306.17 h60
  text "5" at 11265.62,5176.27 h60
  text "MIN. TRACK WIDTH:" at 10187.46,5174.05 h60
  text "MIL" at 11438.46,5174.05 h60
  text "5" at 11274.12,5055.86 h60
  text "MIN. CLEARANCE:" at 10187.46,5049.92 h60
  text "MIL" at 11438.46,5049.92 h60
  text "MIN. VIA PAD SIZE:" at 10187.46,4925.8 h60
  text "16" at 11253.71,4925.8 h60
  text "MIL" at 11438.46,4925.8 h60
  text "0.05mm (2MIL)" at 10882.46,4795.9 h60
  text "MINIMUM ANNULAR RING" at 9858.23,4787.67 h60
  text "EXTERNAL" at 11590.46,4787.67 h60
  text "PER" at 10058.23,4677.55 h60
  text "IPC-D-275 CLASS 2 LEVEL C" at 10278.23,4677.54 h60
  text "MIL, HOLES" at 11766.46,4577.07 h60
  text "+/-" at 11374,4568.48 h60
  text "+/-" at 12228,4568.48 h60
  text "REGISTRATION TOLERANCES:" at 9858.23,4567.42 h60
  text "METAL" at 11058,4567.42 h60
  text "5" at 11634.2,4567.42 h60
  text "3" at 12467.2,4567.42 h60
  text "MIL" at 12583.46,4567.42 h60
  text "HOLE SIZE TOLERANCE (UNLESS OTHERWISE SPECIFIED):" at 9858.23,4469.1 h60
  text "+/-" at 12228,4466.23 h60
  text "3" at 12467.2,4465.17 h60
  text "MIL" at 12583.46,4465.17 h60
  text "MATERIAL:" at 9783.46,4327.52 h60
  text "FR-4 High Tg" at 10769.9,4199 h60
  text "X" at 10625.46,4191.01 h60
  text "FR-408" at 10204.46,4186.49 h60
  text "OTHER" at 11692.46,4186.49 h60
  text "62 MIL (1.6mm) +/-10%" at 10524.56,4043.46 h60
  text "X" at 10404.46,4041.01 h60
  text "THICKNESS:" at 9858.23,4035.24 h60
  text "OTHER" at 11809.46,4035.24 h60
  text "TOLERANCE:" at 9858.23,3896.92 h60
  text "X" at 10706.46,3896.92 h60
  text "ANSI IPC-6012 TYPE 3 CLASS 2" at 10884.47,3896.92 h60
  text "OTHER +/-" at 10884.46,3752.73 h60
  text "BOW & TWIST:" at 9858.23,3607.54 h60
  text "X" at 10706.46,3607.54 h60
  text "ANSI IPC-6012 TYPE 3 CLASS 2" at 10884.47,3607.54 h60
  text "OTHER +/-" at 10884.46,3460.85 h60
  text "DRILLING:" at 9783.46,3330.23 h60
  text "NC_DRILL FILES" at 11544.46,3225.04 h60
  text "REFERENCE:" at 9858.23,3221.1 h60
  text "X" at 10515.46,3221.01 h60
  text "AS SHOWN" at 10693.46,3221.1 h60
  text "X" at 11416.46,3221.1 h60
  text "OTHER" at 11842.46,3078.85 h60
  text "PTH COPPER THICKNESS:" at 9857.9,3075.32 h60
  text "X" at 10997.14,3075.32 h60
  text "20-30 um" at 11125.14,3075.32 h60
  text "BOARD FINISH:" at 9783.46,2927.73 h60
  text "SILKSCREEN:" at 9938.68,2817.6 h60
  text "X" at 10896.46,2817.6 h60
  text "TOP" at 11013.46,2817.6 h60
  text "X" at 11406.46,2817.6 h60
  text "BOTTOM" at 11524.46,2817.6 h60
  text "SILKSCREEN COLOR:" at 9938.68,2662.41 h60
  text "X" at 10895.46,2662.41 h60
  text "WHITE" at 11013.46,2662.41 h60
  text "OTHER" at 11524.46,2662.41 h60
  text "X" at 11026.46,2518.96 h60
  text "GREEN" at 11144.46,2518.96 h60
  text "OTHER" at 11762.46,2518.96 h60
  text "SOLDER RESIST COLOR:" at 9938.68,2512.1 h60
  text "X" at 11026.46,2364.71 h60
  text "MATTE" at 11144.46,2364.71 h60
  text "SEMI-GLOSS" at 11762,2364.07 h60
  text "IMMERSION GOLD (ENIG)" at 10844.46,2191.94 h60
  text "ENEPIG" at 12182,2184.72 h60
  text "SURFACE FINISH:" at 9783.46,2183.72 h60
  text "X" at 10666.46,2183.72 h60
  text "IMM. TIN/SILVER OR EQUIV" at 10113,2046.4 h60
  text "OTHER" at 11544.46,2042.47 h60
  text "ARRAY/PANEL:" at 9783.46,1887.09 h60
  text "X" at 10666.96,1885.2 h60
  text "CUT AND TRIM PER M1 BOARD OUTLINE" at 10844.46,1878.87 h60
  text "N.C. ROUTE" at 10844.46,1742.9 h60
  text "V. SCORE" at 11710.46,1742.9 h60
  text "CERTIFICATION:" at 9783.46,1613.77 h60
  text "MATERIALS AND WORKMANSHIP FOR ALL PCBS" at 10508.46,1613.77 h60
  text "TO MEET OR EXCEED THE REQUIREMENTS OF:" at 10508.46,1519.71 h60
  text "X" at 10145.97,1391.08 h60
  text "ANSI IPC-A-600F CLASS ->" at 10273.96,1391.08 h60
  text "X" at 11921.97,1391.08 h60
  text "2" at 12031.96,1391.08 h60
  text "1" at 11716.96,1389.58 h60
  text "3" at 12385.96,1389.58 h60
  text "X" at 10957.97,1243.39 h60
  text "RoHS" at 11085.96,1243.39 h60
  text "OTHER" at 11730.36,1243.39 h60
  text "PER ORDER" at 12127.42,1243.39 h60
  text "ALL BOARDS MUST MEET OR EXCEED UL94-V0 REQUIREMENTS." at 9811,1089.57 h60
  text "PCB MUST BEAR THE UL94V-0 UL REGISTERED MATERIAL ID NUMBER" at 9811,973.5 h60
  text "ADDITIONAL REQUIREMENTS:" at 9783.46,804.08 h60
  text "MICROSECTION:" at 9858.23,696.95 h60
  text "YES" at 10763.96,696.95 h60
  text "REQUIRED" at 11625.46,552.62 h60
  text "BARE BOARD ELEC. TEST:" at 9858.23,549.76 h60
  text "NONE" at 11163.96,549.76 h60
  text "X" at 11507.46,549.76 h60
  text "PER ORDER" at 12217.46,549.76 h60
  text "XX MIL VIAS REQUIRE NON-CONDUCTIVE FILL AND PLANARIZE" at 10026.38,344.82 h59
  text "XX MIL VIAS REQUIRE CONDUCTIVE FILL AND PLANARIZE" at 10034.38,240.84 h60
  text "OUTER XX MIL TRACES REQUIRE 50 OHM SINGLE-ENDED IMPEDANCE" at 10033.39,77.46 h58
  text "LAYER 2 & 3 (INNER LAYERS) XX MIL WIDE, XX MIL SPACE / TRACES REQUIRE 100 OHM DIFFERENTIAL IMPEDANCE" at 10025.39,-158.26 h60
  text ".Layer_Name" at -973,-1908.49 h60
M11 Gerber Information:
  lines w10: -1842,-1980.17 4758,-1980.17 ; -1842,-1776.83 4760,-1776.83 ; -1842,-1573.5 -1842,-2183.5 2163,-2183.5 4760,-2183.5 4760,-1573.5 -1841.5,-1573.5 -1841.5,-2183.5 -266,-2183.5 ; 623,-2183.5 623,-1573.5 ; 1890,-1667.4 1890,-1573.5 ; 2730,-1776.83 2730,-1573.5 ; 3352,-2190 3352,-1987.17
  text "REV:" at 2092.4,-1659.47 h60
  text "A" at 2383.9,-1659.47 h60
  text "ALL ARTWORK VIEWED FROM TOP SIDE" at -1778.5,-1705.67 h60
  text "BOARD #:" at 698,-1705.67 h60
  text "SVN REV:" at 2926,-1705.67 h60
  text ".VersionControl_RevNumber" at 3432,-1705.67 h60
  text "REF80x_Breakout_CouponCard_Cut" at 1167.6,-1738.77 h50
  text "LAYER NAME =" at -1778.5,-1908.49 h60
  text "TID #:" at 698,-1909 h60
  text ".TID" at 1243.5,-1909 h60
  text ".plot_File_Name" at -1124.8,-2101.84 h40
  text "PLOT NAME =" at -1778.5,-2114.34 h60
  text "GENERATED    :" at 700,-2114.34 h60
  text ".Print_Date" at 1569.5,-2114.34 h60
  text ".Print_Time" at 2298.5,-2114.34 h60
  text "TEXAS INSTRUMENTS" at 3563,-2114.34 h60
M12 Stackup:
  text ".Layer_Name" at -973,-1908.49 h60
M13 Component Bodies Top:
  text ".Layer_Name" at -973,-1908.49 h60
M14 Component Bodies Bottom:
  text ".Layer_Name" at -973,-1908.49 h60
M15 Courtyards Top:
  text ".Layer_Name" at -973,-1908.49 h60
M16 Courtyards Bottom:
  text ".Layer_Name" at -973,-1908.49 h60
Drill Drawing:
  drawing of 184 lines, arcs and shapes, not listed
  text "Symbol" at 5555.59,1585.83 h72
  text "Count" at 5856.16,1585.83 h72
  text "Hole Size" at 6155.58,1585.83 h72
  text "Plated" at 6745.49,1585.83 h72
  text "Hole Type" at 7004.63,1585.83 h72
  text "Drill Layer Pair" at 7379.79,1585.83 h72
  text "Hole Tolerance" at 8104.12,1585.83 h72
  text "4" at 5856.16,1461.51 h60
  text "7.87mil (0.200mm)" at 6155.58,1461.51 h60
  text "PTH" at 6745.49,1461.51 h60
  text "Round" at 7004.63,1461.51 h60
  text "Top Layer - Bottom Layer" at 7379.79,1461.51 h60
  text "B" at 5530.31,1451.52 h55.25
  text "10" at 5856.16,1337.19 h60
  text "8.00mil (0.203mm)" at 6155.58,1337.19 h60
  text "PTH" at 6745.49,1337.19 h60
  text "Round" at 7004.63,1337.19 h60
  text "Top Layer - Bottom Layer" at 7379.79,1337.19 h60
  text "19" at 5856.16,1212.87 h60
  text "12.00mil (0.305mm)" at 6155.58,1212.87 h60
  text "PTH" at 6745.49,1212.87 h60
  text "Round" at 7004.63,1212.87 h60
  text "Top Layer - Bottom Layer" at 7379.79,1212.87 h60
  text "9" at 5856.16,1088.55 h60
  text "16.00mil (0.406mm)" at 6155.58,1088.55 h60
  text "PTH" at 6745.49,1088.55 h60
  text "Round" at 7004.63,1088.55 h60
  text "Top Layer - Bottom Layer" at 7379.79,1088.55 h60
  text "4" at 5856.16,964.23 h60
  text "16.00mil (0.406mm)" at 6155.58,964.23 h60
  text "NPTH" at 6745.49,964.23 h60
  text "Slot" at 7004.63,964.23 h60
  text "Top Layer - Bottom Layer" at 7379.79,964.23 h60
  text "8" at 5856.16,839.91 h60
  text "16.00mil (0.406mm)" at 6155.58,839.91 h60
  text "NPTH" at 6745.49,839.91 h60
  text "Slot" at 7004.63,839.91 h60
  text "Top Layer - Bottom Layer" at 7379.79,839.91 h60
  text "2" at 5856.16,715.59 h60
  text "16.00mil (0.406mm)" at 6155.58,715.59 h60
  text "NPTH" at 6745.49,715.59 h60
  text "Slot" at 7004.63,715.59 h60
  text "Top Layer - Bottom Layer" at 7379.79,715.59 h60
  text "4" at 5856.16,591.27 h60
  text "16.00mil (0.406mm)" at 6155.58,591.27 h60
  text "NPTH" at 6745.49,591.27 h60
  text "Slot" at 7004.63,591.27 h60
  text "Top Layer - Bottom Layer" at 7379.79,591.27 h60
  text "4" at 5856.16,466.95 h60
  text "16.00mil (0.406mm)" at 6155.58,466.95 h60
  text "NPTH" at 6745.49,466.95 h60
  text "Slot" at 7004.63,466.95 h60
  text "Top Layer - Bottom Layer" at 7379.79,466.95 h60
  text "2" at 5856.16,342.63 h60
  text "27.56mil (0.700mm)" at 6155.58,342.63 h60
  text "PTH" at 6745.49,342.63 h60
  text "Round" at 7004.63,342.63 h60
  text "Top Layer - Bottom Layer" at 7379.79,342.63 h60
  text "4" at 5856.16,218.31 h60
  text "31.50mil (0.800mm)" at 6155.58,218.31 h60
  text "PTH" at 6745.49,218.31 h60
  text "Round" at 7004.63,218.31 h60
  text "Top Layer - Bottom Layer" at 7379.79,218.31 h60
  text "5" at 5856.16,93.99 h60
  text "33.47mil (0.850mm)" at 6155.58,93.99 h60
  text "PTH" at 6745.49,93.99 h60
  text "Round" at 7004.63,93.99 h60
  text "Top Layer - Bottom Layer" at 7379.79,93.99 h60
  text "14" at 5856.16,-30.33 h60
  text "40.16mil (1.020mm)" at 6155.58,-30.33 h60
  text "PTH" at 6745.49,-30.33 h60
  text "Round" at 7004.63,-30.33 h60
  text "Top Layer - Bottom Layer" at 7379.79,-30.33 h60
  text "2" at 5856.16,-154.65 h60
  text "124.02mil (3.150mm)" at 6155.58,-154.65 h60
  text "PTH" at 6745.49,-154.65 h60
  text "Round" at 7004.63,-154.65 h60
  text "Top Layer - Bottom Layer" at 7379.79,-154.65 h60
  text "4" at 5856.16,-278.97 h60
  text "125.00mil (3.175mm)" at 6155.58,-278.97 h60
  text "PTH" at 6745.49,-278.97 h60
  text "Round" at 7004.63,-278.97 h60
  text "Top Layer - Bottom Layer" at 7379.79,-278.97 h60
  text "D" at 5530.31,-288.96 h55.25
  text "4" at 5856.16,-403.29 h60
  text "125.98mil (3.200mm)" at 6155.58,-403.29 h60
  text "PTH" at 6745.49,-403.29 h60
  text "Round" at 7004.63,-403.29 h60
  text "Top Layer - Bottom Layer" at 7379.79,-403.29 h60
  text "2" at 5856.16,-527.61 h60
  text "144.00mil (3.658mm)" at 6155.58,-527.61 h60
  text "PTH" at 6745.49,-527.61 h60
  text "Round" at 7004.63,-527.61 h60
  text "Top Layer - Bottom Layer" at 7379.79,-527.61 h60
  text "101 Total" at 5856.16,-651.93 h60
  text "Slot definitions :" at 5555.59,-738.95 h60
  text "Routed Path Length" at 6006.31,-738.95 h60
  text "= Calculated from tool start centre position to tool end centre position." at 6546.05,-738.95 h60
  text "Hole Length" at 6006.31,-788.68 h60
  text "= Routed Path Length + Tool Size = Slot length as defined in the PCB layout" at 6346.24,-788.68 h60
  text ".Layer_Name" at -973,-1908.49 h60
M17 Embedded Cavity:
  lines w20: 1918.65,2828.62 1918.65,2543.62 2253.65,2543.62 ; 1968.65,2723.62 1968.65,3058.62 2253.65,3058.62 ; 2148.65,2493.62 2433.65,2493.62 2433.65,2828.62 ; 2148.65,3008.62 2483.65,3008.62 2483.65,2723.62
  text ".Layer_Name" at -973,-1908.49 h60
M18 Embedded Assembly:
  lines w20: 1840.65,2603.12 1840.65,2415.62 2028.15,2415.62 ; 1840.65,2673.12 1840.65,2879.12 ; 1840.65,2949.12 1840.65,3136.62 2028.15,3136.62 ; 2098.15,2415.62 2178.15,2415.62 ; 2098.15,3136.62 2178.15,3136.62 ; 2224.15,2415.62 2304.15,2415.62 ; 2224.15,3136.62 2304.15,3136.62 ; 2374.15,2415.62 2561.65,2415.62 2561.65,2603.12 ; 2374.15,3136.62 2561.65,3136.62 2561.65,2949.12 ; 2561.65,2673.12 2561.65,2879.12
  text ".Layer_Name" at -973,-1908.49 h60
M19 Embedded Keepout:
  text ".Layer_Name" at -973,-1908.49 h60

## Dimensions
4050,140 to 4027.14,4844.07 on M2 Board Dimensions
-1758.07,-910.83 to -758.07,-910.83 on M2 Board Dimensions
4027.14,4844.07 to 36.73,4844.13 on M2 Board Dimensions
